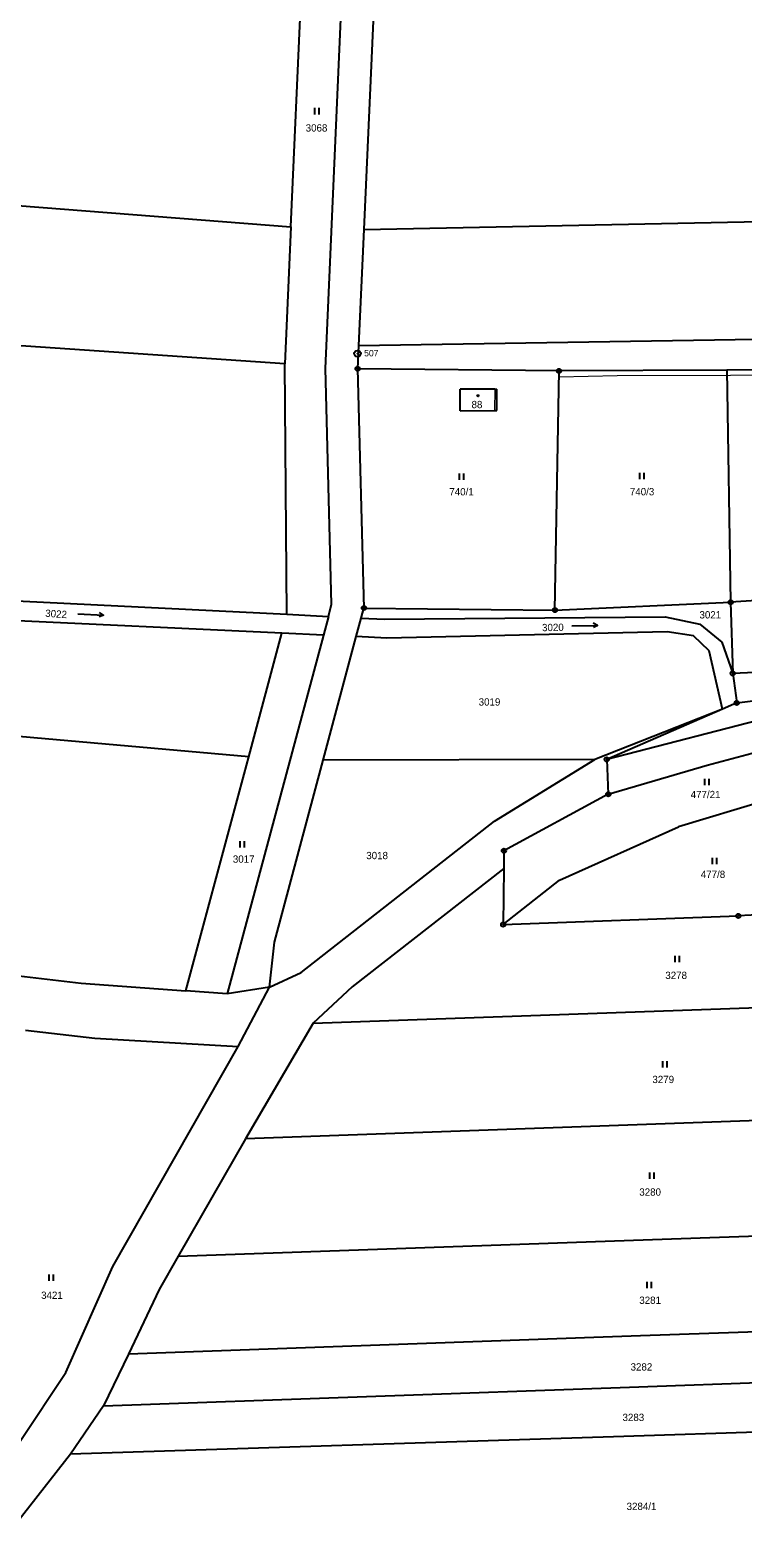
# Model space of a CAD drawing. Extents: x -618848 to -615803, y -1044450 to -1042254.
# Drawn here: x -617478.1 to -617311.9, y -1043290.2 to -1042938.5 of the extents above; entities that cross this region are included whole.
import ezdxf
from ezdxf.enums import TextEntityAlignment as Align

# ---------------------------------------------------------------- set-up
doc = ezdxf.new("R2010")
doc.units = 0
doc.header["$LTSCALE"] = 0.68
for name, color, linetype, lineweight in [('1', 7, 'Continuous', 25), ('13', 7, 'Continuous', 13), ('3', 7, 'Continuous', 25), ('4', 7, 'Continuous', 13), ('5', 7, 'Continuous', 25), ('8', 7, 'Continuous', 25)]:
    doc.layers.add(name, color=color, linetype=linetype, lineweight=lineweight)
doc.layers.add('2', color=7, linetype='Continuous')

msp = doc.modelspace()

# ---------------------------------------------------------------- linework, layer by layer
at = {"layer": '1'}
for p, q in [((-617409.26, -1043017.42), (-617402.12, -1042856.16)), ((-617417.33, -1042984.44), (-617414.94, -1042930.49)), ((-617397.93, -1042931.09), (-617400.32, -1042985.03)), ((-617595.55, -1042970.52), (-617417.33, -1042984.44)), ((-617400.32, -1042985.03), (-617297.31, -1042982.96)), ((-617417.33, -1042984.44), (-617418.74, -1043016.34)), ((-617400.32, -1042985.03), (-617401.52, -1043012.05)), ((-617418.74, -1043016.34), (-617528.9, -1043008.9)), ((-617401.52, -1043012.05), (-617207.42, -1043009.06)), ((-617401.52, -1043012.05), (-617401.76, -1043017.49)), ((-617418.27, -1043074.77), (-617418.74, -1043016.34)), ((-617407.82, -1043072.41), (-617409.26, -1043017.42)), ((-617354.79, -1043018.01), (-617401.76, -1043017.49)), ((-617401.76, -1043017.49), (-617400.29, -1043073.3)), ((-617355.73, -1043073.77), (-617354.79, -1043018.01)), ((-617315.65, -1043017.84), (-617354.79, -1043018.01)), ((-617294.49, -1043017.75), (-617315.65, -1043017.84)), ((-617315.65, -1043017.84), (-617314.79, -1043071.95)), ((-617377.82, -1043027.3), (-617377.82, -1043022.28)), ((-617369.76, -1043022.28), (-617377.82, -1043022.28)), ((-617369.76, -1043022.28), (-617369.3, -1043022.28)), ((-617369.3, -1043027.23), (-617369.3, -1043022.28)), ((-617377.82, -1043027.3), (-617369.8, -1043027.23)), ((-617369.8, -1043027.23), (-617369.3, -1043027.23)), ((-617250.92, -1043067.62), (-617314.79, -1043071.95)), ((-617492.79, -1043071.09), (-617418.27, -1043074.77)), ((-617408.58, -1043075.25), (-617407.82, -1043072.41)), ((-617400.92, -1043075.64), (-617400.29, -1043073.3)), ((-617400.29, -1043073.3), (-617355.73, -1043073.77)), ((-617355.73, -1043073.77), (-617314.79, -1043071.95)), ((-617314.79, -1043071.95), (-617314.26, -1043088.54)), ((-617419.46, -1043079.18), (-617492.92, -1043075.77)), ((-617418.27, -1043074.77), (-617408.58, -1043075.25)), ((-617408.58, -1043075.25), (-617409.75, -1043079.63)), ((-617402.08, -1043079.98), (-617400.92, -1043075.64)), ((-617400.92, -1043075.64), (-617395.5, -1043075.91)), ((-617395.5, -1043075.91), (-617330.07, -1043075.32)), ((-617330.07, -1043075.32), (-617321.97, -1043077.1)), ((-617321.97, -1043077.1), (-617316.82, -1043081.28)), ((-617409.75, -1043079.63), (-617432.15, -1043163.3)), ((-617427.17, -1043107.98), (-617419.46, -1043079.18)), ((-617409.75, -1043079.63), (-617419.46, -1043079.18)), ((-617409.8, -1043108.82), (-617402.08, -1043079.98)), ((-617394.93, -1043080.32), (-617402.08, -1043079.98)), ((-617329.54, -1043078.83), (-617394.93, -1043080.32)), ((-617323.43, -1043079.78), (-617329.54, -1043078.83)), ((-617319.74, -1043083.29), (-617323.43, -1043079.78)), ((-617316.82, -1043081.28), (-617314.26, -1043088.54)), ((-617316.7, -1043096.88), (-617319.74, -1043083.29)), ((-617247.11, -1043085.8), (-617314.26, -1043088.54)), ((-617314.26, -1043088.54), (-617313.34, -1043095.42)), ((-617274.14, -1043090.62), (-617343.65, -1043108.61)), ((-617313.34, -1043095.42), (-617274.14, -1043090.62)), ((-617313.34, -1043095.42), (-617316.7, -1043096.88)), ((-617427.17, -1043107.98), (-617554.76, -1043096.68)), ((-617316.7, -1043096.88), (-617346.4, -1043108.62)), ((-617316.7, -1043096.88), (-617343.65, -1043108.61)), ((-617320.24, -1043109.95), (-617271.09, -1043096.78)), ((-617441.79, -1043162.58), (-617427.17, -1043107.98)), ((-617421.15, -1043151.22), (-617409.8, -1043108.82)), ((-617346.4, -1043108.62), (-617409.8, -1043108.82)), ((-617369.81, -1043123), (-617346.4, -1043108.62)), ((-617343.65, -1043108.61), (-617343.32, -1043116.74)), ((-617343.32, -1043116.74), (-617320.24, -1043109.95)), ((-617343.32, -1043116.74), (-617367.64, -1043129.9)), ((-617306.79, -1043118.3), (-617326.96, -1043124.37)), ((-617414.92, -1043158.33), (-617369.81, -1043123)), ((-617354.66, -1043136.75), (-617326.96, -1043124.37)), ((-617367.64, -1043129.9), (-617367.68, -1043134.02)), ((-617367.68, -1043134.02), (-617403, -1043161.62)), ((-617367.68, -1043134.02), (-617367.82, -1043147.12)), ((-617367.82, -1043147.12), (-617354.66, -1043136.75)), ((-617277.71, -1043143.39), (-617313, -1043145.1)), ((-617367.82, -1043147.12), (-617313, -1043145.1)), ((-617422.34, -1043161.72), (-617421.15, -1043151.22)), ((-617542.83, -1043151.92), (-617466.23, -1043160.76)), ((-617422.34, -1043161.72), (-617414.92, -1043158.33)), ((-617466.23, -1043160.76), (-617441.79, -1043162.58)), ((-617422.34, -1043161.72), (-617432.15, -1043163.3)), ((-617429.65, -1043175.55), (-617422.34, -1043161.72)), ((-617403, -1043161.62), (-617412.15, -1043170.15)), ((-617432.15, -1043163.3), (-617441.79, -1043162.58)), ((-617412.15, -1043170.15), (-617261.54, -1043164.8)), ((-617479.19, -1043171.76), (-617463.07, -1043173.59)), ((-617412.15, -1043170.15), (-617427.92, -1043197.08)), ((-617463.07, -1043173.59), (-617429.65, -1043175.55)), ((-617458.84, -1043226.86), (-617429.65, -1043175.55)), ((-617237.59, -1043190.31), (-617427.92, -1043197.08)), ((-617427.92, -1043197.08), (-617443.58, -1043224.49)), ((-617328.52, -1043220.4), (-617213.45, -1043216.31)), ((-617443.58, -1043224.49), (-617328.52, -1043220.4)), ((-617443.58, -1043224.49), (-617448.01, -1043232.24)), ((-617469.85, -1043251.63), (-617458.84, -1043226.86)), ((-617448.01, -1043232.24), (-617455.2, -1043247.32)), ((-617216.36, -1043238.84), (-617335.78, -1043243.08)), ((-617335.78, -1043243.08), (-617455.2, -1043247.32)), ((-617455.2, -1043247.32), (-617461.01, -1043259.37)), ((-617480.44, -1043267.57), (-617469.85, -1043251.63)), ((-617338.34, -1043255.02), (-617215.66, -1043250.66)), ((-617461.01, -1043259.37), (-617338.34, -1043255.02)), ((-617461.01, -1043259.37), (-617468.72, -1043270.64)), ((-617264.81, -1043264.08), (-617342.05, -1043266.56)), ((-617342.05, -1043266.56), (-617468.72, -1043270.64)), ((-617468.72, -1043270.64), (-617484.37, -1043290.59))]:
    msp.add_line(p, q, dxfattribs=at)
at = {"layer": '13'}
msp.add_lwpolyline([(-617354.78, -1043019.42), (-617341.22, -1043019.09), (-617314.8, -1043019.02), (-617304.3, -1043018.9), (-617294.89, -1043018.86), (-617276.59, -1043018.79), (-617262.39, -1043018.72), (-617251.59, -1043018.67), (-617251.16, -1043053.01), (-617250.92, -1043067.62), (-617247.41, -1043067.35), (-617247.63, -1043052.93), (-617249.66, -1043017.56), (-617263.26, -1043017.62), (-617294.49, -1043017.75), (-617315.65, -1043017.84), (-617354.79, -1043018.01)], close=True, dxfattribs=at)
at = {"layer": '3'}
for p, q in [((-617411.731, -1042958.17), (-617411.731, -1042956.67)), ((-617410.73, -1042958.17), (-617410.73, -1042956.67)), ((-617378.021, -1043043.4), (-617378.021, -1043041.9)), ((-617377.02, -1043043.4), (-617377.02, -1043041.9)), ((-617335.971, -1043043.27), (-617335.971, -1043041.77)), ((-617334.97, -1043043.27), (-617334.97, -1043041.77)), ((-617461.037, -1043074.936), (-617462.039, -1043075.386)), ((-617345.813, -1043077.346), (-617346.781, -1043077.864)), ((-617320.751, -1043114.65), (-617320.751, -1043113.15)), ((-617319.75, -1043114.65), (-617319.75, -1043113.15)), ((-617429.131, -1043129.14), (-617429.131, -1043127.64)), ((-617428.13, -1043129.14), (-617428.13, -1043127.64)), ((-617319.011, -1043133.07), (-617319.011, -1043131.57)), ((-617318.01, -1043133.07), (-617318.01, -1043131.57)), ((-617327.731, -1043155.89), (-617327.731, -1043154.39)), ((-617326.73, -1043155.89), (-617326.73, -1043154.39)), ((-617330.591, -1043180.49), (-617330.591, -1043178.99)), ((-617329.59, -1043180.49), (-617329.59, -1043178.99)), ((-617333.631, -1043206.42), (-617333.631, -1043204.92)), ((-617332.63, -1043206.42), (-617332.63, -1043204.92)), ((-617473.661, -1043230.23), (-617473.661, -1043228.73)), ((-617472.66, -1043230.23), (-617472.66, -1043228.73)), ((-617334.261, -1043231.92), (-617334.261, -1043230.42)), ((-617333.26, -1043231.92), (-617333.26, -1043230.42))]:
    msp.add_line(p, q, dxfattribs=at)
for points in [[(-617467.029, -1043074.622), (-617461.037, -1043074.936), (-617461.987, -1043074.385)], [(-617351.812, -1043077.451), (-617345.813, -1043077.346), (-617346.799, -1043076.862)]]:
    msp.add_lwpolyline(points, dxfattribs=at)
at = {"layer": '4'}
msp.add_line((-617369.76, -1043022.28), (-617369.8, -1043027.23), dxfattribs=at)
at = {"layer": '5'}
msp.add_circle((-617373.6768, -1043023.7992), 0.175, dxfattribs=at)
at = {"layer": '8'}
for centre, radius in [((-617401.78, -1043013.9798), 0.75), ((-617401.78, -1043013.9798), 0.03), ((-617401.76, -1043017.4899), 0.5), ((-617401.76, -1043017.4899), 0.0303), ((-617354.79, -1043018.0099), 0.5), ((-617354.79, -1043018.0099), 0.0303), ((-617400.29, -1043073.2999), 0.5), ((-617400.29, -1043073.2999), 0.0303), ((-617355.73, -1043073.7699), 0.5), ((-617355.73, -1043073.7699), 0.0303), ((-617314.79, -1043071.9499), 0.5), ((-617314.79, -1043071.9499), 0.0303), ((-617314.26, -1043088.5399), 0.5), ((-617314.26, -1043088.5399), 0.0303), ((-617313.34, -1043095.4199), 0.5), ((-617313.34, -1043095.4199), 0.0303), ((-617343.65, -1043108.6099), 0.5), ((-617343.65, -1043108.6099), 0.0303), ((-617343.32, -1043116.7399), 0.5), ((-617343.32, -1043116.7399), 0.0303), ((-617367.64, -1043129.8999), 0.5), ((-617367.64, -1043129.8999), 0.0303), ((-617313, -1043145.0999), 0.5), ((-617367.82, -1043147.1199), 0.5), ((-617367.82, -1043147.1199), 0.0303), ((-617313, -1043145.0999), 0.0303)]:
    msp.add_circle(centre, radius, dxfattribs=at)

# ---------------------------------------------------------------- texts
at = {"layer": '2'}
for s, p in [('3068', (-617413.87, -1042962.185)), ('3021', (-617322.03, -1043075.735)), ('3019', (-617373.53, -1043096.055)), ('3018', (-617399.74, -1043131.875)), ('3017', (-617430.86, -1043132.705)), ('3278', (-617330, -1043159.815)), ('3279', (-617333.01, -1043184.095)), ('3280', (-617336.07, -1043210.355)), ('3421', (-617475.58, -1043234.425)), ('3281', (-617336.07, -1043235.585)), ('3282', (-617338.1, -1043251.135)), ('3283', (-617339.98, -1043262.905))]:
    msp.add_text(s, height=1.7, dxfattribs=at).set_placement(p)
for s, p in [('88', (-617373.929, -1043026.695)), ('740/1', (-617377.53, -1043047.035)), ('740/3', (-617335.42, -1043047.015)), ('477/21', (-617320.61, -1043117.645)), ('477/8', (-617318.88, -1043136.255)), ('3284/1', (-617335.55, -1043283.665))]:
    msp.add_text(s, height=1.7, dxfattribs=at).set_placement(p, align=Align.CENTER)
for s, rotation, p in [('3022', 356, (-617474.659, -1043075.333)), ('3020', 1, (-617358.732, -1043078.714))]:
    msp.add_text(s, height=1.7, rotation=rotation, dxfattribs=at).set_placement(p)
at = {"layer": '8'}
msp.add_text('507', height=1.5, dxfattribs=at).set_placement((-617400.24, -1043014.605))

doc.saveas('drawing.dxf')
